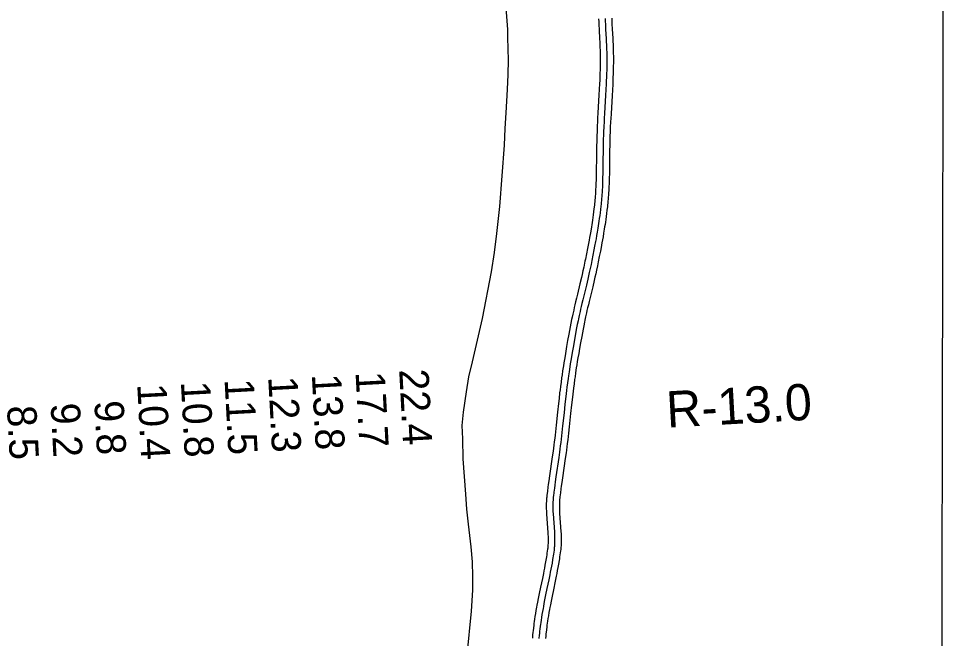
# Model space of a CAD drawing. Extents: x 3192952 to 3230831, y 849296 to 874698.
# Drawn here: x 3210731 to 3212870, y 858041 to 859457 of the extents above; entities that cross this region are included whole.
import ezdxf

# ---------------------------------------------------------------- set-up
doc = ezdxf.new("R2010")
doc.units = 0
for name, color, linetype in [('V-GRID-MAJR', 7, 'Continuous'), ('V-RIVR-RANG', 7, 'Continuous'), ('V-RIVR-RANG-IDEN', 7, 'Continuous'), ('V-ROAD-CNTR', 7, 'Continuous'), ('V-SITE-VEGE', 7, 'Continuous'), ('V-TOPO-SHOR', 7, 'Continuous')]:
    doc.layers.add(name, color=color, linetype=linetype)

msp = doc.modelspace()

# ---------------------------------------------------------------- linework, layer by layer
at = {"layer": 'V-GRID-MAJR'}
msp.add_spline([(3212836, 854703.6), (3212847.5, 860762.7), (3212858.9, 866825.2), (3212870.4, 872887.8), (3212870.4, 872891.2)], degree=3, dxfattribs=at)
at = {"layer": 'V-ROAD-CNTR'}
for points in [[(3212057, 859456.7), (3212057.3, 859450), (3212057.6, 859443.6), (3212058.2, 859431.7), (3212059.3, 859411), (3212059.7, 859403.2), (3212060, 859396.5), (3212060.2, 859390.6), (3212060.4, 859385.5), (3212060.6, 859381), (3212060.7, 859377.1), (3212060.8, 859370.3), (3212060.9, 859365.2), (3212060.9, 859361.4), (3212060.8, 859355.6), (3212060.7, 859349.9), (3212060.5, 859340.6), (3212060.2, 859331.8), (3212059.9, 859323.5), (3212059.5, 859315.8), (3212059.2, 859308.5), (3212058.5, 859294.9), (3212057.8, 859283), (3212055.4, 859241), (3212054.8, 859230.4), (3212054.4, 859222.5), (3212053.9, 859210.7), (3212053.4, 859198.7), (3212053.1, 859190.3), (3212052.8, 859182.5), (3212052.7, 859175.1), (3212052.5, 859168.2), (3212052.3, 859155.2), (3212052, 859132.7), (3212051.8, 859115.9), (3212051.6, 859103.3), (3212051.3, 859093.9), (3212051.1, 859086.9), (3212050.9, 859081.6), (3212050.6, 859073.7), (3212050.2, 859065.8), (3212049.9, 859060.9), (3212049.6, 859056.1), (3212049.3, 859051.5), (3212048.9, 859047), (3212048.5, 859042.6), (3212048.1, 859038.4), (3212047.7, 859034.3), (3212047.3, 859030.4), (3212046.4, 859022.7), (3212045.6, 859015.5), (3212044.7, 859008.8), (3212043.8, 859002.4), (3212042.9, 858996.5), (3212042.1, 858990.9), (3212041.3, 858985.7), (3212040.5, 858980.9), (3212039, 858971.7), (3212037.6, 858963.7), (3212036.4, 858956.6), (3212035.2, 858950.5), (3212033.2, 858939.7), (3212031.7, 858931.6), (3212029.3, 858919.5), (3212026.9, 858907.4), (3212025.9, 858902.6), (3212025, 858898), (3212023.1, 858889), (3212021.2, 858880.6), (3212019.4, 858872.7), (3212017.7, 858865.3), (3212014.4, 858851.4), (3212008.5, 858827.1), (3212006.3, 858817.9), (3212004.4, 858809.9), (3212002.7, 858802.8), (3212001.3, 858796.7), (3212000.1, 858791.2), (3211998, 858781.7), (3211996.4, 858774.6), (3211995.3, 858769.2), (3211993.6, 858761.1), (3211992.1, 858753), (3211988.9, 858736), (3211986.2, 858721.2), (3211983.9, 858708.2), (3211981.9, 858696.8)], [(3212072, 859457.4), (3212072.3, 859450.6), (3212072.5, 859444.3), (3212073.1, 859432.5), (3212074.3, 859411.7), (3212074.7, 859404), (3212075, 859397.2), (3212075.2, 859391.2), (3212075.4, 859386), (3212075.6, 859381.5), (3212075.7, 859377.5), (3212075.8, 859370.5), (3212075.9, 859365.3), (3212075.9, 859361.3), (3212075.8, 859355.5), (3212075.7, 859349.6), (3212075.5, 859340.1), (3212075.2, 859331.2), (3212074.9, 859322.9), (3212074.5, 859315.1), (3212074.2, 859307.8), (3212073.5, 859294.1), (3212072.8, 859282.1), (3212070.4, 859240.1), (3212069.8, 859229.6), (3212069.4, 859221.8), (3212068.8, 859210), (3212068.4, 859198.2), (3212068.1, 859189.9), (3212067.8, 859182.1), (3212067.7, 859174.7), (3212067.5, 859167.9), (3212067.3, 859155), (3212067, 859132.5), (3212066.8, 859115.6), (3212066.6, 859103), (3212066.3, 859093.5), (3212066.1, 859086.4), (3212065.9, 859081), (3212065.6, 859073), (3212065.2, 859065), (3212064.9, 859060), (3212064.6, 859055.1), (3212064.2, 859050.3), (3212063.8, 859045.7), (3212063.5, 859041.3), (3212063.1, 859037), (3212062.6, 859032.8), (3212062.2, 859028.8), (3212061.3, 859020.9), (3212060.4, 859013.6), (3212059.5, 859006.8), (3212058.7, 859000.3), (3212057.8, 858994.3), (3212056.9, 858988.7), (3212056.1, 858983.4), (3212055.3, 858978.4), (3212053.8, 858969.2), (3212052.4, 858961.1), (3212051.1, 858954), (3212050, 858947.8), (3212048, 858936.9), (3212046.4, 858928.8), (3212044, 858916.6), (3212041.6, 858904.4), (3212040.6, 858899.6), (3212039.7, 858894.9), (3212037.7, 858885.8), (3212035.8, 858877.3), (3212034, 858869.3), (3212032.3, 858861.9), (3212029, 858848), (3212023.1, 858823.6), (3212020.9, 858814.4), (3212019, 858806.4), (3212017.3, 858799.4), (3212015.9, 858793.3), (3212014.7, 858787.9), (3212012.6, 858778.5), (3212011.1, 858771.4), (3212010, 858766.1), (3212008.4, 858758.2), (3212006.8, 858750.2), (3212003.7, 858733.3), (3212001, 858718.5), (3211998.7, 858705.6), (3211996.7, 858694.3)], [(3212087, 859458), (3212087.2, 859451.3), (3212087.5, 859445), (3212088.1, 859433.2), (3212089.2, 859412.5), (3212089.6, 859404.7), (3212090, 859397.8), (3212090.2, 859391.8), (3212090.4, 859386.5), (3212090.6, 859381.9), (3212090.7, 859377.8), (3212090.8, 859370.7), (3212090.9, 859365.4), (3212090.9, 859361.3), (3212090.8, 859355.3), (3212090.7, 859349.2), (3212090.5, 859339.7), (3212090.2, 859330.7), (3212089.9, 859322.3), (3212089.5, 859314.4), (3212089.2, 859307.1), (3212088.5, 859293.3), (3212087.8, 859281.3), (3212085.4, 859239.3), (3212084.8, 859228.8), (3212084.4, 859221), (3212083.8, 859209.3), (3212083.3, 859197.6), (3212083, 859189.4), (3212082.8, 859181.7), (3212082.7, 859174.4), (3212082.5, 859167.6), (3212082.3, 859154.8), (3212082, 859132.3), (3212081.8, 859115.4), (3212081.6, 859102.7), (3212081.3, 859093.1), (3212081.1, 859085.9), (3212080.9, 859080.5), (3212080.6, 859072.3), (3212080.2, 859064.2), (3212079.9, 859059), (3212079.5, 859054), (3212079.2, 859049.2), (3212078.8, 859044.5), (3212078.4, 859039.9), (3212078, 859035.5), (3212077.6, 859031.3), (3212077.1, 859027.1), (3212076.2, 859019.2), (3212075.3, 859011.7), (3212074.4, 859004.8), (3212073.5, 858998.2), (3212072.6, 858992.1), (3212071.8, 858986.4), (3212070.9, 858981.1), (3212070.1, 858976), (3212068.6, 858966.7), (3212067.1, 858958.5), (3212065.9, 858951.3), (3212064.7, 858945), (3212062.7, 858934.1), (3212061.1, 858926), (3212058.7, 858913.7), (3212056.3, 858901.5), (3212055.3, 858896.6), (3212054.3, 858891.8), (3212052.4, 858882.6), (3212050.5, 858874), (3212048.6, 858866), (3212046.9, 858858.5), (3212043.6, 858844.5), (3212037.7, 858820.1), (3212035.5, 858810.9), (3212033.6, 858803), (3212032, 858796), (3212030.5, 858789.9), (3212029.3, 858784.6), (3212027.3, 858775.3), (3212025.8, 858768.3), (3212024.7, 858763.1), (3212023.1, 858755.2), (3212021.5, 858747.4), (3212018.4, 858730.6), (3212015.7, 858715.9), (3212013.4, 858703), (3212011.5, 858691.7)], [(3211981.9, 858696.8), (3211980.2, 858686.8), (3211978.8, 858678.1), (3211977.5, 858670.4), (3211976.5, 858663.7), (3211974.7, 858652), (3211973.4, 858643.1), (3211972.4, 858636.5), (3211971.1, 858626.5), (3211969.8, 858616.6), (3211968.9, 858609.1), (3211968, 858602.1), (3211966.5, 858589.1), (3211965.2, 858577.6), (3211963.1, 858557.6), (3211959.9, 858527.8), (3211958.3, 858512.9), (3211957.4, 858505.5), (3211956.6, 858498.1), (3211955.6, 858490), (3211954.6, 858482.4), (3211953.7, 858475.3), (3211952.8, 858468.6), (3211951, 858456.1), (3211944.7, 858412.1), (3211943.1, 858401), (3211941.9, 858392.7), (3211941.1, 858386.5), (3211939.9, 858377.1), (3211938.7, 858367.6), (3211938.5, 858365.6), (3211938.3, 858363.5), (3211938.1, 858361.4), (3211937.8, 858357.5), (3211937.6, 858353.7), (3211937.5, 858350), (3211937.4, 858346.4), (3211937.4, 858343), (3211937.4, 858339.7), (3211937.5, 858336.5), (3211937.6, 858333.4), (3211937.7, 858330.4), (3211938, 858324.6), (3211941, 858283.1), (3211941.3, 858278.2), (3211941.4, 858273.9), (3211941.5, 858270.2), (3211941.5, 858266.9), (3211941.5, 858264.1), (3211941.5, 858261.6), (3211941.4, 858259.5), (3211941.4, 858257.6), (3211941.2, 858254.3), (3211941, 858251.9), (3211940.9, 858250.1), (3211940.6, 858247.4), (3211940.3, 858244.7), (3211939.6, 858240.2), (3211939, 858235.8), (3211938.4, 858231.6), (3211937.7, 858227.4), (3211937.1, 858223.5), (3211935.8, 858215.7), (3211934.4, 858208.4), (3211933.2, 858201.6), (3211931.9, 858195.2), (3211930.7, 858189.2), (3211928.4, 858177.9), (3211924.3, 858158), (3211921.2, 858143.1), (3211918.9, 858131.8), (3211917.2, 858123.3), (3211916, 858116.9), (3211915.1, 858112), (3211913.8, 858104.8), (3211912.6, 858097.5), (3211911.5, 858090.7), (3211910.6, 858084.7), (3211909.9, 858079.5), (3211909.2, 858074.9), (3211908.7, 858070.9), (3211907.8, 858063.9), (3211907.2, 858058.7), (3211906.8, 858054.7), (3211906.2, 858048.8), (3211905.6, 858042.8), (3211905.5, 858041.5)], [(3211996.7, 858694.3), (3211995, 858684.3), (3211993.6, 858675.7), (3211992.3, 858668.1), (3211991.3, 858661.4), (3211989.5, 858649.7), (3211988.2, 858641), (3211987.3, 858634.4), (3211985.9, 858624.6), (3211984.7, 858614.7), (3211983.7, 858607.3), (3211982.9, 858600.4), (3211981.4, 858587.4), (3211980.1, 858576), (3211978, 858556), (3211974.8, 858526.2), (3211973.2, 858511.2), (3211972.3, 858503.8), (3211971.5, 858496.3), (3211970.5, 858488.1), (3211969.5, 858480.5), (3211968.6, 858473.3), (3211967.6, 858466.6), (3211965.9, 858454), (3211959.5, 858410), (3211957.9, 858398.9), (3211956.8, 858390.7), (3211956, 858384.5), (3211954.8, 858375.2), (3211953.6, 858365.9), (3211953.4, 858364), (3211953.2, 858362.1), (3211953, 858360.2), (3211952.8, 858356.6), (3211952.6, 858353), (3211952.5, 858349.6), (3211952.4, 858346.3), (3211952.4, 858343.1), (3211952.4, 858339.9), (3211952.5, 858336.9), (3211952.6, 858333.9), (3211952.7, 858331.1), (3211953, 858325.6), (3211956, 858284.1), (3211956.3, 858278.9), (3211956.4, 858274.4), (3211956.5, 858270.4), (3211956.5, 858266.9), (3211956.5, 858263.9), (3211956.5, 858261.3), (3211956.4, 858258.9), (3211956.3, 858256.9), (3211956.2, 858253.4), (3211956, 858250.7), (3211955.8, 858248.7), (3211955.5, 858245.8), (3211955.1, 858242.8), (3211954.5, 858238.1), (3211953.9, 858233.6), (3211953.2, 858229.3), (3211952.5, 858225.1), (3211951.9, 858221), (3211950.5, 858213.1), (3211949.2, 858205.7), (3211947.9, 858198.8), (3211946.6, 858192.3), (3211945.4, 858186.3), (3211943.1, 858174.9), (3211939, 858155), (3211935.9, 858140.1), (3211933.6, 858128.8), (3211932, 858120.4), (3211930.8, 858114.1), (3211929.9, 858109.4), (3211928.6, 858102.2), (3211927.4, 858095.1), (3211926.3, 858088.4), (3211925.5, 858082.5), (3211924.7, 858077.4), (3211924.1, 858072.9), (3211923.6, 858069), (3211922.7, 858062.1), (3211922.1, 858057), (3211921.7, 858053.1), (3211921.1, 858047.3), (3211920.5, 858041.5), (3211920.5, 858040.5)], [(3212011.5, 858691.7), (3212009.8, 858681.9), (3212008.4, 858673.2), (3212007.2, 858665.7), (3212006.1, 858659.1), (3212004.4, 858647.5), (3212003.1, 858638.8), (3212002.2, 858632.3), (3212000.8, 858622.6), (3211999.5, 858612.8), (3211998.6, 858605.5), (3211997.8, 858598.6), (3211996.3, 858585.7), (3211995, 858574.4), (3211992.9, 858554.5), (3211989.7, 858524.5), (3211988.1, 858509.6), (3211987.2, 858502), (3211986.4, 858494.5), (3211985.4, 858486.3), (3211984.4, 858478.6), (3211983.4, 858471.3), (3211982.5, 858464.5), (3211980.7, 858451.9), (3211974.4, 858407.8), (3211972.8, 858396.9), (3211971.7, 858388.7), (3211970.8, 858382.5), (3211969.6, 858373.3), (3211968.5, 858364.1), (3211968.3, 858362.4), (3211968.1, 858360.7), (3211968, 858359), (3211967.7, 858355.6), (3211967.6, 858352.4), (3211967.5, 858349.2), (3211967.4, 858346.1), (3211967.4, 858343.1), (3211967.4, 858340.2), (3211967.5, 858337.3), (3211967.6, 858334.5), (3211967.7, 858331.8), (3211968, 858326.5), (3211971, 858285), (3211971.2, 858279.5), (3211971.4, 858274.8), (3211971.5, 858270.6), (3211971.5, 858267), (3211971.5, 858263.7), (3211971.5, 858260.9), (3211971.4, 858258.4), (3211971.3, 858256.2), (3211971.1, 858252.4), (3211970.9, 858249.6), (3211970.7, 858247.4), (3211970.4, 858244.1), (3211970, 858240.9), (3211969.4, 858236.1), (3211968.7, 858231.5), (3211968, 858227), (3211967.4, 858222.7), (3211966.7, 858218.5), (3211965.3, 858210.5), (3211963.9, 858203), (3211962.6, 858196), (3211961.4, 858189.4), (3211960.1, 858183.3), (3211957.8, 858171.9), (3211953.7, 858151.9), (3211950.6, 858137.1), (3211948.3, 858125.9), (3211946.7, 858117.6), (3211945.5, 858111.3), (3211944.6, 858106.7), (3211943.4, 858099.7), (3211942.2, 858092.6), (3211941.2, 858086.1), (3211940.3, 858080.3), (3211939.6, 858075.3), (3211939, 858070.9), (3211938.5, 858067.1), (3211937.6, 858060.3), (3211937, 858055.3), (3211936.6, 858051.5), (3211936, 858045.8), (3211935.5, 858040.3)]]:
    msp.add_lwpolyline(points, dxfattribs=at)
at = {"layer": 'V-SITE-VEGE'}
for p, q in [((3211844.1, 859491.6), (3211849, 859432.2)), ((3211849, 859432.2), (3211848.9, 859413.7)), ((3211848.9, 859413.7), (3211849.9, 859362.1)), ((3211849.9, 859362.1), (3211849.7, 859329.1)), ((3211849.7, 859329.1), (3211848.2, 859294.7)), ((3211848.2, 859294.7), (3211845.2, 859241.9)), ((3211845.2, 859241.9), (3211842.4, 859206.2)), ((3211842.4, 859206.2), (3211840.8, 859167.9)), ((3211840.8, 859167.9), (3211830.7, 859027.9)), ((3211830.7, 859027.9), (3211823.7, 858965.8)), ((3211823.7, 858965.8), (3211818.2, 858922.3)), ((3211818.2, 858922.3), (3211811.3, 858878.7)), ((3211811.3, 858878.7), (3211790.8, 858771.8)), ((3211790.8, 858771.8), (3211767.8, 858672.8)), ((3211767.8, 858672.8), (3211759.6, 858638.5)), ((3211759.6, 858638.5), (3211754.1, 858604.2)), ((3211754.1, 858604.2), (3211747.3, 858558)), ((3211747.3, 858558), (3211744.4, 858527.6)), ((3211744.4, 858527.6), (3211745.6, 858497.2)), ((3211745.6, 858497.2), (3211746.6, 858451)), ((3211746.6, 858451), (3211752.7, 858370.3)), ((3211752.7, 858370.3), (3211755.2, 858335.9)), ((3211755.2, 858335.9), (3211758.9, 858301.6)), ((3211758.9, 858301.6), (3211765.2, 858250)), ((3211765.2, 858250), (3211767.6, 858215.6)), ((3211767.6, 858215.6), (3211768.8, 858182.6)), ((3211768.8, 858182.6), (3211768.6, 858150.9)), ((3211768.6, 858150.9), (3211765.6, 858103.3)), ((3211765.6, 858103.3), (3211755.8, 858002.9))]:
    msp.add_line(p, q, dxfattribs=at)
at = {"layer": 'V-TOPO-SHOR'}
msp.add_lwpolyline([(3211844.1, 859491.6), (3211849, 859432.2), (3211848.9, 859413.7), (3211849.9, 859362.1), (3211849.7, 859329.1), (3211848.2, 859294.7), (3211845.2, 859241.9), (3211842.4, 859206.2), (3211840.8, 859167.9), (3211830.7, 859027.9), (3211823.7, 858965.8), (3211818.2, 858922.3), (3211811.3, 858878.7), (3211790.8, 858771.8), (3211767.8, 858672.8), (3211759.6, 858638.5), (3211754.1, 858604.2), (3211747.3, 858558), (3211744.4, 858527.6), (3211745.6, 858497.2), (3211746.6, 858451), (3211752.7, 858370.3), (3211755.2, 858335.9), (3211758.9, 858301.6), (3211765.2, 858250), (3211767.6, 858215.6), (3211768.8, 858182.6), (3211768.6, 858150.9), (3211765.6, 858103.3), (3211755.8, 858002.9)], dxfattribs=at)

# ---------------------------------------------------------------- texts
at = {"layer": 'V-RIVR-RANG'}
for s, p in [('22.4', (3211600.9, 858655)), ('12.3', (3211301.4, 858638.3)), ('13.8', (3211401.2, 858643.9)), ('17.7', (3211501.1, 858649.4)), ('10.4', (3211001.9, 858621.6)), ('10.8', (3211101.7, 858627.1)), ('11.5', (3211201.6, 858632.7)), ('8.5', (3210704.1, 858571.7)), ('9.2', (3210803.9, 858577.2)), ('9.8', (3210903.8, 858582.8))]:
    msp.add_text(s, height=67, rotation=273.0483, dxfattribs=at).set_placement(p)
at = {"layer": 'V-RIVR-RANG-IDEN'}
msp.add_text('R-13.0', height=83, rotation=3.1949, dxfattribs=at).set_placement((3212214.1, 858522.2))

doc.saveas('drawing.dxf')
